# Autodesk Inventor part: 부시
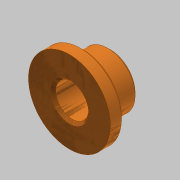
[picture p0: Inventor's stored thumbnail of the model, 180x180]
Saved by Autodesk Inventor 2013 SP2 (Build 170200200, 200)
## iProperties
Created: 2016-02
Part Number: 부시
Material: 스테인리스강
Document SubType Name: Modeling
Designer: mduedu
Density: 8.08 g/cm^3
Author: mduedu
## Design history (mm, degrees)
sketch "스케치1"
  geometry: C1 r 15 at (0, 0); 1 further point
  constraints: 1 centre point, 1 coincident
  dimensions: "d0" = 30 diameter of C1
extrude "돌출1" new body sketch "스케치1" distance "d1" = 5; taper "d2" = 0 deg
sketch "스케치2"
  geometry: C1 r 10 at (0, 0); 1 further point
  constraints: 1 centre point, 1 coincident
  dimensions: "d3" = 20 diameter of C1
extrude "돌출2" join sketch "스케치2" distance "d4" = 10; taper "d5" = 0 deg
hole "구멍1" diameter "d8" = 12; stored, may be unused: countersink angle "d12" = 90 deg, drill point angle "d14" = 118 deg; dims "d9" = 6, "d10" = 4, "d11" = 2, "d13" = 8, "d15" = 10, "d16" = 10
chamfer "모따기1" distance "d17" = 1; stored, may be unused: second distance "d18" = 2, angle "d19" = 45 deg
chamfer "모따기2" distance "d20" = 1; stored, may be unused: second distance "d21" = 2, angle "d22" = 45 deg
chamfer "모따기3" distance "d23" = 1; stored, may be unused: second distance "d24" = 2, angle "d25" = 45 deg
node "솔리드1"
